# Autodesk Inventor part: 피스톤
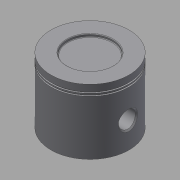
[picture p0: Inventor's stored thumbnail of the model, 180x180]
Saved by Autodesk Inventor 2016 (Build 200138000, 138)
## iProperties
Created: 2016-11
Part Number: 피스톤
Material: 강철, 탄소
Document SubType Name: Modeling
Designer: mduedu
Density: 7.87 g/cm^3
Mass: 273.351 g
Surface Area: 265.015 cm^2
Volume: 34.7333 cm^3
Appearance: 기본값
Author: mduedu
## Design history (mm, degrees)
sketch "스케치1"
  geometry: C1 r 30 at (0, 0); 1 further point
  constraints: 1 centre point, 1 coincident
  dimensions: "d0" = 60 diameter of C1
extrude "돌출1" new body sketch "스케치1" distance "d1" = 50; taper "d2" = 0 deg
sketch "스케치2"
  geometry: C1 r 28 at (0, 0); 1 further point
  constraints: 1 centre point, 1 coincident
  dimensions: "d3" = 56 diameter of C1
extrude "돌출2" cut sketch "스케치2" distance "d4" = 45; taper "d5" = 0 deg
sketch "스케치3"
  geometry: L1 (30, 0)-(30, 50) reference; L2 (30, 45)-(29, 45); L3 (29, 45)-(29, 44); L4 (29, 44)-(30, 44); L5 (30, 44)-(30, 45); L6 (30, 43)-(29, 43); L7 (29, 43)-(29, 42); L8 (29, 42)-(30, 42); L9 (30, 42)-(30, 43); L10 (30, 50)-(-30, 50) reference; L11 (0, 50)-(0, 0)
  constraints: 18 end point, 4 parallel, 3 equal length, 3 perpendicular, 2 horizontal, 2 point on line, 1 midpoint
  dimensions: "d6" = 1 distance of L2.start L2.end; "d8" = 5 distance between parallel lines of L10 L2; "d9" = 1 distance between parallel lines of L6 L4
revolve "회전1" sketch "스케치3" stored, may be unused: angle "d10" = 90 deg
node "작업 평면1"
sketch "스케치4"
  geometry: C1 r 10 at (20, 0); C2 r 6.5 at (20, 0); 1 further point
  constraints: 2 centre point, 1 coincident, 1 horizontal alignment
  dimensions: "d12" = 20 diameter of C1; "d13" = 13 diameter of C2; "d14" = 20 distance of point (0, 0) C1.centre
extrude "돌출3" join sketch "스케치4" stored distance "d15" = 11.75; taper "d16" = 0 deg
extrude "돌출4" cut sketch "스케치4" stored distance "d17" = 72; taper "d18" = 0 deg
fillet "모깎기1" dims "d19" = 3
fillet "모깎기2" dims "d20" = 3
chamfer "모따기1" distance "d21" = 1; stored, may be unused: second distance "d22" = 2, angle "d23" = 45 deg
chamfer "모따기2" distance "d24" = 1; stored, may be unused: second distance "d25" = 2, angle "d26" = 45 deg
sketch "스케치5"
  geometry: C1 r 17.5 at (0, 0); 1 further point
  constraints: 1 centre point, 1 coincident
  dimensions: "d27" = 35 diameter of C1
extrude "돌출5" cut sketch "스케치5" distance "d28" = 2; taper "d29" = 0 deg
fillet "모깎기3" dims "d30" = 0.5
node "솔리드1"
mirror "대칭1"
